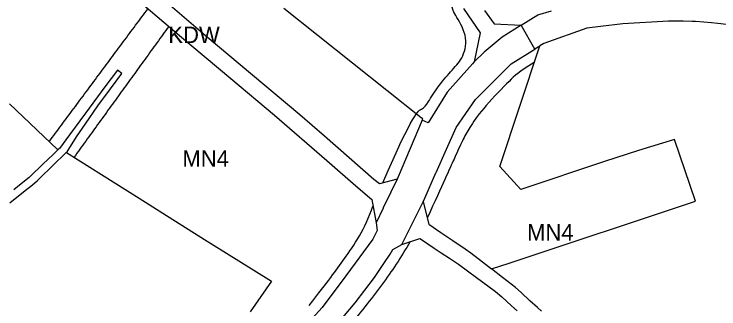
# Model space of a CAD drawing. Extents: x 7413438 to 7416393, y 5541665 to 5544118.
# Drawn here: x 7414186.3 to 7414442.9, y 5542752 to 5542859.3 of the extents above; entities that cross this region are included whole.
import ezdxf

# ---------------------------------------------------------------- set-up
doc = ezdxf.new("R2010")
doc.units = 0
for name, color, linetype in [('linie_rozgraniczajace', 7, 'Continuous'), ('linie_zabudowy_nieprzekraczalne', 7, 'Continuous'), ('oznaczenia_przeznaczen', 7, 'Continuous')]:
    doc.layers.add(name, color=color, linetype=linetype)

msp = doc.modelspace()

# ---------------------------------------------------------------- linework, layer by layer
at = {"layer": 'linie_rozgraniczajace'}
for p, q in [((7414255.9, 5542851.55), (7414225.35, 5542877.76)), ((7414228.73, 5542866.78), (7414246.56, 5542851.56)), ((7414334.49, 5542821.6), (7414284.48, 5542861.39)), ((7414349.96, 5542861.38), (7414355.97, 5542852.55)), ((7414357.54, 5542860.63), (7414361.08, 5542855.72)), ((7414370.95, 5542855.31), (7414377, 5542859.07)), ((7414377, 5542859.07), (7414381.99, 5542860.47)), ((7414424.51, 5542856.76), (7414407.92, 5542855.74)), ((7414429.86, 5542856.7), (7414424.51, 5542856.76)), ((7414433.13, 5542856.67), (7414429.86, 5542856.7)), ((7414434.38, 5542856.57), (7414433.13, 5542856.67)), ((7414437.34, 5542856.36), (7414434.38, 5542856.57)), ((7414440.2, 5542856.17), (7414437.34, 5542856.36)), ((7414361.08, 5542855.72), (7414370.95, 5542855.31)), ((7414370.95, 5542855.31), (7414363.93, 5542850.94)), ((7414375.88, 5542846.6), (7414370.95, 5542855.31)), ((7414394.79, 5542854.19), (7414379.16, 5542848.64)), ((7414399.81, 5542854.78), (7414394.79, 5542854.19)), ((7414407.92, 5542855.74), (7414399.81, 5542854.78)), ((7414442.48, 5542855.92), (7414440.2, 5542856.17)), ((7414445.59, 5542855.49), (7414442.48, 5542855.92)), ((7414246.56, 5542851.56), (7414265.25, 5542835.88)), ((7414290.38, 5542822.68), (7414255.9, 5542851.55)), ((7414355.97, 5542852.55), (7414353.83, 5542841.89)), ((7414363.93, 5542850.94), (7414357.38, 5542845.49)), ((7414363.13, 5542803.92), (7414377.67, 5542847.71)), ((7414367.28, 5542841.25), (7414375.88, 5542846.6)), ((7414377.64, 5542847.69), (7414375.88, 5542846.6)), ((7414377.67, 5542847.71), (7414377.64, 5542847.69)), ((7414379.16, 5542848.64), (7414377.67, 5542847.71)), ((7414357.38, 5542845.49), (7414353.83, 5542841.89)), ((7414353.13, 5542841.21), (7414343.99, 5542830.89)), ((7414353.14, 5542841.19), (7414353.13, 5542841.21)), ((7414353.83, 5542841.89), (7414353.14, 5542841.19)), ((7414354.27, 5542828.19), (7414367.28, 5542841.25)), ((7414223.94, 5542838.95), (7414219.39, 5542832.8)), ((7414225.54, 5542837.76), (7414223.94, 5542838.95)), ((7414221.38, 5542832.13), (7414225.54, 5542837.76)), ((7414265.25, 5542835.88), (7414281.17, 5542822.57)), ((7414219.39, 5542832.8), (7414212.32, 5542823.24)), ((7414216.82, 5542825.97), (7414221.38, 5542832.13)), ((7414343.99, 5542830.89), (7414337.07, 5542819.72)), ((7414347.28, 5542818.03), (7414354.27, 5542828.19)), ((7414184.6, 5542826.64), (7414202.12, 5542810.03)), ((7414212.27, 5542819.39), (7414216.82, 5542825.97)), ((7414212.32, 5542823.24), (7414206.53, 5542815.41)), ((7414281.17, 5542822.57), (7414300.22, 5542806.08)), ((7414299.3, 5542814.87), (7414290.38, 5542822.68)), ((7414334.88, 5542820.73), (7414326.13, 5542800.1)), ((7414335.06, 5542821.15), (7414334.49, 5542821.6)), ((7414334.88, 5542820.73), (7414335.06, 5542821.15)), ((7414337.07, 5542819.72), (7414334.88, 5542820.73)), ((7414208.98, 5542814.63), (7414212.27, 5542819.39)), ((7414343.76, 5542810.22), (7414347.28, 5542818.03)), ((7414206.53, 5542815.41), (7414202.88, 5542810.47)), ((7414205.59, 5542809.2), (7414208.98, 5542814.63)), ((7414308.31, 5542806.97), (7414299.3, 5542814.87)), ((7414426.75, 5542813.7), (7414413.65, 5542809.69)), ((7414434.34, 5542791.2), (7414426.75, 5542813.7)), ((7414202.55, 5542810.27), (7414200.5, 5542808.27)), ((7414202.12, 5542810.03), (7414202.69, 5542810.43)), ((7414202.69, 5542810.43), (7414202.55, 5542810.27)), ((7414202.81, 5542810.51), (7414202.69, 5542810.43)), ((7414202.88, 5542810.47), (7414202.81, 5542810.51)), ((7414339.92, 5542801.69), (7414343.76, 5542810.22)), ((7414200.5, 5542808.27), (7414196.78, 5542804.65)), ((7414200.97, 5542804.78), (7414204.54, 5542808.22)), ((7414204.54, 5542808.22), (7414205.31, 5542808.98)), ((7414205.31, 5542808.98), (7414205.34, 5542808.96)), ((7414205.34, 5542808.96), (7414205.59, 5542809.2)), ((7414205.34, 5542808.96), (7414218.14, 5542800.92)), ((7414413.65, 5542809.69), (7414401.29, 5542805.73)), ((7414300.22, 5542806.08), (7414310.75, 5542796.85)), ((7414317.23, 5542799.15), (7414308.31, 5542806.97)), ((7414401.29, 5542805.73), (7414370.75, 5542795.47)), ((7414196.78, 5542804.65), (7414192.14, 5542800.23)), ((7414194.78, 5542798.78), (7414200.97, 5542804.78)), ((7414370.75, 5542795.47), (7414363.13, 5542803.92)), ((7414192.14, 5542800.23), (7414191.79, 5542799.89)), ((7414218.14, 5542800.92), (7414231.81, 5542792.34)), ((7414326.13, 5542800.1), (7414325.73, 5542799.26)), ((7414335.88, 5542792.36), (7414339.8, 5542801.58)), ((7414339.8, 5542801.58), (7414339.92, 5542801.69)), ((7414188.91, 5542797.58), (7414186.21, 5542795.42)), ((7414191.79, 5542799.89), (7414188.91, 5542797.58)), ((7414193.07, 5542797.19), (7414194.78, 5542798.78)), ((7414319.29, 5542797.55), (7414317.23, 5542799.15)), ((7414325.73, 5542799.26), (7414319.29, 5542797.55)), ((7414325.73, 5542799.26), (7414323.43, 5542794.48)), ((7414184.82, 5542790.69), (7414190.4, 5542795.09)), ((7414190.4, 5542795.09), (7414193.07, 5542797.19)), ((7414310.75, 5542796.85), (7414316.49, 5542791.9)), ((7414231.81, 5542792.34), (7414231.85, 5542792.31)), ((7414231.85, 5542792.31), (7414240.47, 5542786.91)), ((7414323.43, 5542794.48), (7414320.7, 5542788.81)), ((7414335.23, 5542791.06), (7414335.88, 5542792.36)), ((7414316.49, 5542791.9), (7414318.07, 5542783.33)), ((7414330.36, 5542781.31), (7414335.23, 5542791.06)), ((7414335.23, 5542791.06), (7414337.29, 5542782.88)), ((7414366.59, 5542768.68), (7414434.34, 5542791.2)), ((7414320.63, 5542788.66), (7414318.07, 5542783.33)), ((7414320.7, 5542788.81), (7414320.63, 5542788.66)), ((7414240.47, 5542786.91), (7414255.68, 5542777.34)), ((7414318.07, 5542783.33), (7414318.49, 5542780.57)), ((7414337.29, 5542782.88), (7414341.7, 5542779.86)), ((7414318.49, 5542780.57), (7414316.86, 5542777.38)), ((7414327.47, 5542775.54), (7414330.36, 5542781.31)), ((7414341.7, 5542779.86), (7414346.01, 5542776.93)), ((7414255.68, 5542777.34), (7414262.63, 5542772.97)), ((7414316.86, 5542777.38), (7414307.13, 5542764.07)), ((7414327.47, 5542775.54), (7414333.99, 5542777.72)), ((7414333.99, 5542777.72), (7414335.36, 5542776.87)), ((7414335.36, 5542776.87), (7414336.93, 5542775.75)), ((7414346.01, 5542776.93), (7414350.56, 5542773.96)), ((7414324.21, 5542773.68), (7414327.47, 5542775.54)), ((7414336.93, 5542775.75), (7414339.25, 5542774.17)), ((7414262.63, 5542772.97), (7414279.97, 5542762.09)), ((7414321.21, 5542768.89), (7414323.25, 5542771.95)), ((7414323.25, 5542771.95), (7414324.21, 5542773.68)), ((7414339.25, 5542774.17), (7414341.84, 5542772.49)), ((7414341.84, 5542772.49), (7414344.84, 5542770.53)), ((7414350.56, 5542773.96), (7414352.53, 5542772.48)), ((7414352.53, 5542772.48), (7414356.8, 5542769.18)), ((7414344.84, 5542770.53), (7414348.14, 5542768.31)), ((7414356.8, 5542769.18), (7414360.06, 5542766.66)), ((7414317.55, 5542763.45), (7414321.21, 5542768.89)), ((7414348.14, 5542768.31), (7414351.39, 5542765.89)), ((7414360.06, 5542766.66), (7414366.59, 5542768.68)), ((7414364.14, 5542763.51), (7414360.06, 5542766.66)), ((7414307.13, 5542764.07), (7414298.48, 5542752.52)), ((7414351.39, 5542765.89), (7414354.67, 5542763.44)), ((7414279.97, 5542762.09), (7414272.26, 5542750.95)), ((7414310.44, 5542754.28), (7414317.55, 5542763.45)), ((7414354.67, 5542763.44), (7414358.72, 5542760.41)), ((7414368.87, 5542759.85), (7414364.14, 5542763.51)), ((7414358.72, 5542760.41), (7414361.51, 5542758.33)), ((7414370.96, 5542758.05), (7414368.87, 5542759.85)), ((7414361.51, 5542758.33), (7414363.92, 5542756.39)), ((7414363.92, 5542756.39), (7414367.44, 5542753.15)), ((7414374.04, 5542755.03), (7414370.96, 5542758.05)), ((7414304.61, 5542747.38), (7414310.44, 5542754.28)), ((7414376.87, 5542752.57), (7414374.04, 5542755.03)), ((7414298.48, 5542752.52), (7414287.75, 5542740.89)), ((7414367.44, 5542753.15), (7414369.4, 5542751.34)), ((7414378.35, 5542751.2), (7414376.87, 5542752.57))]:
    msp.add_line(p, q, dxfattribs=at)
at = {"layer": 'linie_zabudowy_nieprzekraczalne'}
for points, degree in [([(7414320.5, 5542797.87), (7414331.67, 5542823.78), (7414335.39, 5542824.67), (7414336.62, 5542826.65), (7414340.94, 5542833.52), (7414345.97, 5542839.2), (7414350.03, 5542843.52), (7414351.66, 5542851.67), (7414346.28, 5542859.68), (7414345.6, 5542862.52), (7414344.9, 5542866.58), (7414345.43, 5542870.43), (7414345.69, 5542871.88)], 3), ([(7414199.06, 5542812.85), (7414235.06, 5542861.31)], 1), ([(7414242.62, 5542854.86), (7414208.09, 5542807.17)], 1), ([(7414375.65, 5542841.76), (7414369.73, 5542838.08), (7414367.74, 5542836.08), (7414357.31, 5542825.6), (7414352.23, 5542818.22), (7414349.85, 5542814.1), (7414347.22, 5542808.26), (7414342.41, 5542797.6), (7414336.69, 5542785.06)], 3), ([(7414293.73, 5542753.31), (7414300.85, 5542762.41), (7414305.65, 5542768.88), (7414314.29, 5542781.22), (7414316.88, 5542789.47)], 3), ([(7414330.5, 5542776.55), (7414327.11, 5542770.73), (7414320.65, 5542760.97), (7414307.51, 5542744.67), (7414295.2, 5542731.39), (7414289.91, 5542726.96), (7414284.38, 5542722.92), (7414270.86, 5542714.31), (7414257.24, 5542706.19), (7414247.85, 5542701.87), (7414232.05, 5542694.6), (7414206.95, 5542682.92), (7414167.63, 5542663.48)], 3)]:
    msp.add_open_spline(points, degree=degree, dxfattribs=at)

# ---------------------------------------------------------------- texts
at = {"layer": 'oznaczenia_przeznaczen'}
for s, p in [('KDW', (7414242.47, 5542848.77)), ('MN4', (7414247.58, 5542803.79)), ('MN4', (7414373.04, 5542776.92))]:
    msp.add_text(s, height=6, dxfattribs=at).set_placement(p)

doc.saveas('drawing.dxf')
